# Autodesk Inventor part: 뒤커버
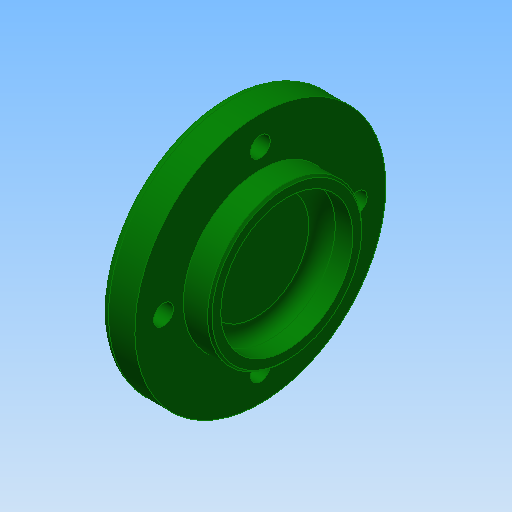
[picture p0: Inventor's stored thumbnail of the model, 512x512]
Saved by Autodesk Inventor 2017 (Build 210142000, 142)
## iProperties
Created: 2015-12
Part Number: 뒤커버
Material: 알루미늄 6061
Document SubType Name: Modeling
Designer: mduedu
Density: 2.71 g/cm^3
Appearance: 진녹색
Author: mduedu
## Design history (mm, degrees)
sketch "스케치1"
  geometry: L1 (0, 0)-(14, 0); L2 (14, 0)-(14, 17.5); L3 (14, 17.5)-(8, 17.5); L4 (8, 17.5)-(8, 28.5); L5 (8, 28.5)-(0, 28.5); L6 (0, 28.5)-(0, 0)
  constraints: 12 end point, 4 parallel, 1 horizontal, 1 perpendicular
  dimensions: "d0" = 14 distance between parallel lines of L2 L6; "d2" = 8 distance of L4.end L5.end; "d3" = 57 diameter of L5 L1; "d4" = 35 diameter of L3 L1
revolve "회전1" sketch "스케치1" stored, may be unused: angle "d5" = 90 deg
hole "구멍1" diameter "d8" = 30; stored, may be unused: countersink angle "d12" = 90 deg, drill point angle "d14" = 0 deg; dims "d9" = 6, "d10" = 4, "d11" = 2, "d13" = 7, "d39" = 10, "d40" = 10
fillet "모깎기3" dims "d38" = 2
fillet "모깎기4" dims "d41" = 3
chamfer "모따기2" distance "d42" = 0.5; stored, may be unused: second distance "d43" = 2, angle "d44" = 45 deg
sketch "스케치2" dims "d45" = 42
  geometry: 6 further points
  constraints: 2 vertical alignment, 1 coincident, 7 other
  dimensions: "d48" = 360 deg dimension on point (0, 0) point (0, 21) (derived)
sketch "스케치3" dims "d57" = 44
  geometry: C1 r 26.5 at (0, 0) reference; 5 further points
  constraints: 1 coincident, 1 horizontal alignment, 2 other
hole "구멍4" sketch "스케치3" at (-22, 0), (0, -22), (22, 0), (0, 22) diameter "d50" = 4.5; stored, may be unused: countersink angle "d54" = 90 deg, drill point angle "d56" = 0 deg; dims "d51" = 6, "d52" = 8, "d53" = 4.6, "d55" = 8
node "솔리드1"
